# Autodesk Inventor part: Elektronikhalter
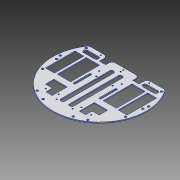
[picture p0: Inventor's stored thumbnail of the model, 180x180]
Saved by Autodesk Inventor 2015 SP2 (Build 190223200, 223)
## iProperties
Created: 2012-08
Part Number: Elektronikhalter
Material: Aluminium 6061
Document SubType Name: Modeling
Designer: rYan
Mass: 66.8945 g
Surface Area: 291.908 cm^2
Volume: 24.6843 cm^3
Density: 2.71 g/cm^3
Appearance: Aluminium - flach
Author: rYan
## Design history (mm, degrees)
sketch "Skizze1" dims "d122" = 174
  geometry: L1 (0, 121.8)-(0, -121.8) reference; L2 (-121.8, 0)-(121.8, 0) reference; L3 (70.484, 51)-(-70.484, 51); A1 r 87 centre (0, 0) between (-70.484, 51) and (70.484, 51); 2 further points
  constraints: 2 coincident, 2 end point, 2 point on circle, 1 centre point, 1 parallel, 3 other
  dimensions: "d27" = 51 distance from line of L3.start L2
extrude "Extrusion1" new body sketch "Skizze1" distance "d5" = 2; taper "d6" = 0 deg
sketch "Skizze2"
  geometry: L1 (0, 78.6)-(0, -114.6) reference; L2 (-121.8, 0)-(121.8, 0) reference; 7 further points
  dimensions: "d7" = 82 distance from line of point (82, 9) L1; "d8" = 9 distance from line of L2 point (82, 9); "d9" = 28 distance from line of point (28, -77) L1; "d10" = 77 distance from line of L2 point (28, -77); "d156" = 80 distance from line of L1 point (80, 0); "d157" = 0 distance from line of point (80, 0) L2; "d200" = 77 distance from line of point (77, -29) L1; "d201" = 29 distance from line of point (77, -29) L2; "d202" = 70 distance from line of point (70, 45) L1; "d203" = 45 distance from line of point (70, 45) L2; "d204" = 69 distance from line of point (47, -69) L2; "d205" = 47 distance from line of point (47, -69) L1
hole "Montagestreben" sketch "Skizze2" at (82, 9), (28, -77), (80, 0), (77, -29), (70, 45), (47, -69) diameter "d11" = 4.2; stored, may be unused: countersink angle "d15" = 90 deg, drill point angle "d17" = 118 deg; dims "d12" = 6, "d13" = 4, "d14" = 2, "d16" = 8
sketch "Skizze4"
  geometry: L1 (0, 78.6)-(0, -114.6) reference; L2 (-121.8, 0)-(121.8, 0) reference; L3 (21, 20)-(21, -55); 2 further points
  constraints: 2 end point, 1 coincident, 1 vertical
  dimensions: "d47" = 21 distance from line of L1 L3.start; "d197" = 55 distance from line of point (21, -55) L2; "d198" = 20 distance from line of L3.start L2
hole "Akku Führung" sketch "Skizze4" at (21, 20), (21, -55) diameter "d48" = 2.459; stored, may be unused: countersink angle "d52" = 90 deg, drill point angle "d54" = 118 deg; dims "d49" = 6, "d50" = 4, "d51" = 2, "d53" = 8
sketch "Skizze5"
  geometry: L1 (0, 78.6)-(0, -114.6) reference; L2 (-121.8, 0)-(121.8, 0) reference; 3 further points
  dimensions: "d134" = 45 distance from line of point (45, 47) L1; "d137" = 42 distance from line of point (42, -58) L1; "d193" = 105 vertical distance of point (42, -58) point (45, 47); "d194" = 47 distance from line of L2 point (45, 47)
hole "Mainboardstreben" sketch "Skizze5" at (45, 47), (42, -58) diameter "d66" = 2.459; stored, may be unused: countersink angle "d70" = 90 deg, drill point angle "d72" = 118 deg; dims "d67" = 6, "d68" = 4, "d69" = 2, "d71" = 8
sketch "Skizze7"
  geometry: L1 (0, 78.6)-(0, -114.6) reference; L2 (-121.8, 0)-(121.8, 0) reference; 3 further points
  constraints: 2 point on line
  dimensions: "d87" = 44 distance from line of L2 point (0, 44); "d179" = 5 distance of point (0, 39) point (0, 44)
hole "Akku Anschlag" sketch "Skizze7" at (0, 44), (0, 39) diameter "d88" = 2.459; stored, may be unused: countersink angle "d92" = 90 deg, drill point angle "d94" = 118 deg; dims "d89" = 6, "d90" = 4, "d91" = 2, "d93" = 8
sketch "Skizze8"
  geometry: L1 (-121.8, 0)-(121.8, 0) reference; L2 (0, 78.6)-(0, -114.6) reference; L3 (15, -65)-(15, 9); 2 further points
  constraints: 2 end point, 1 coincident
  dimensions: "d116" = 9 distance from line of L1 point (15, 9); "d142" = 15 distance between parallel lines of L2 L3; "d143" = 74 distance of point (15, 9) L3.start
hole "Kickeroptionen" sketch "Skizze8" at (15, 9), (15, -65) diameter "d102" = 2.459; stored, may be unused: countersink angle "d106" = 90 deg, drill point angle "d108" = 118 deg; dims "d103" = 6, "d104" = 4, "d105" = 2, "d107" = 8
sketch "Skizze13"
  geometry: L1 (-55, 30)-(-30, 30); L2 (-30, 30)-(-30, -24); L3 (-30, -24)-(-55, -24); L4 (-55, -24)-(-55, 30); L5 (0, 78.6)-(0, -114.6) reference; L6 (-121.8, 0)-(121.8, 0) reference; L7 (-59, 30)-(-76, 30); L8 (-76, 30)-(-76, -25); L9 (-76, -25)-(-59, -25); L10 (-59, -25)-(-59, 30); L11 (-26, 8)-(-22, 8); L12 (-22, 8)-(-22, -24); L13 (-22, -24)-(-26, -24); L14 (-26, -24)-(-26, 8); L15 (70.484, 51)-(-70.484, 51) reference; L16 (-23.509, 51)-(-37, 51); L17 (-37, 51)-(-37, 36); L18 (-37, 36)-(-25, 36); L19 (-25, 36)-(-25, 48); L20 (-50, -35)-(-25, -35); L21 (-25, -35)-(-25, -63); L22 (-37, -51)-(-50, -51); L23 (-50, -51)-(-50, -35); L24 (-25, 48)-(0, 48); L25 (0, 48)-(0, 51); L26 (0, 51)-(-23.509, 51); L27 (-8, 30)-(-8, -60); L28 (-12, 30)-(-12, -60); L29 (-4, -60)-(-4, 30); L30 (-65, 39)-(-45, 39); L31 (-65, 35)-(-45, 35); L32 (-45, 43)-(-65, 43); L33 (-37, -51)-(-37, -63); L34 (-37, -63)-(-25, -63); A1 r 4 centre (-8, 30) between (-4, 30) and (-12, 30); A2 r 4 centre (-8, -60) between (-12, -60) and (-4, -60); A3 r 4 centre (-65, 39) between (-65, 43) and (-65, 35); A4 r 4 centre (-45, 39) between (-45, 35) and (-45, 43); 3 further points
  constraints: 66 end point, 15 parallel, 8 point on circle, 8 tangent, 7 horizontal, 7 perpendicular, 4 centre point, 3 midpoint, 2 collinear, 1 point on line
  dimensions: "d158" = 54 distance of L1.end L2.end; "d159" = 25 distance of L1.start L1.end; "d160" = 30 distance between parallel lines of L5 L2; "d161" = 30 distance between parallel lines of L6 L1; "d164" = 4 distance between parallel lines of L10 L4; "d165" = 17 distance of L7.start L7.end; "d166" = 4 distance between parallel lines of L2 L14 (derived); "d168" = 4 distance of L11.start L11.end; "d169" = 55 distance of L7.end L8.end; "d171" = 12 distance of L17.end L18.end; "d172" = 15 distance of L16.end L17.end; "d173" = 25 distance between parallel lines of L5 L19; "d174" = 25 distance between parallel lines of L5 L21; "d175" = 35 distance between parallel lines of L6 L20; "d176" = 25 distance of L20.start L20.end; "d177" = 16 distance of L22.end L20.start; "d182" = 3 distance between parallel lines of L26 L24; "d183" = 90 distance of L27.start L27.end; "d184" = 8 distance between parallel lines of L27 L5; "d185" = 4 radius of A1; "d186" = 15 distance from line of point (-8, -15) L6; "d187" = 20 distance of L30.start L30.end; "d188" = 4 radius of A4; "d189" = 55 distance from line of L5 point (-55, 39); "d190" = 12 distance between parallel lines of L15 L30; "d195" = 12 distance of L33.end L21.end; "d196" = 12 distance of L22.start L33.end; "d199" = 22 distance between parallel lines of L1 L11
extrude "Extrusion2" cut sketch "Skizze13" stored distance "d162" = 10; taper "d163" = 0 deg
mirror "Spiegeln1"
fillet "Rundung1" dims "d191" = 6
fillet "Rundung2" dims "d192" = 1
node "Volumenkörper1"
